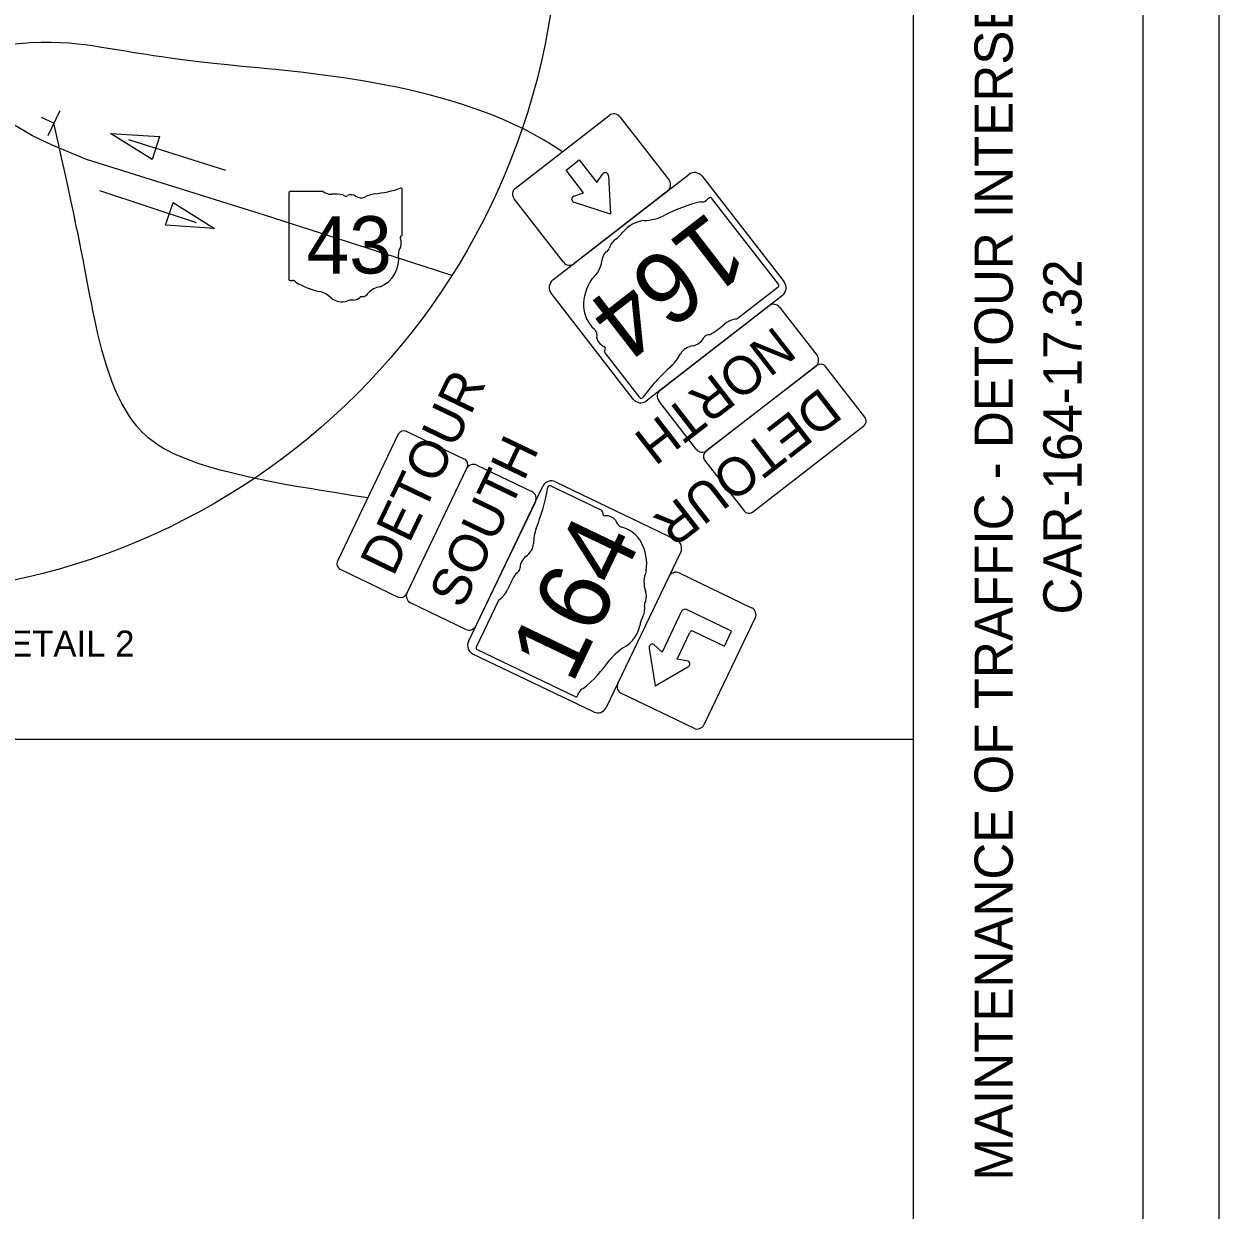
# Model space of a CAD drawing. Extents: x -202 to 1556, y 0 to 676.
# Drawn here: x 523.6 to 680, y 158.4 to 313.6 of the extents above; entities that cross this region are included whole.
import ezdxf

# ---------------------------------------------------------------- set-up
doc = ezdxf.new("R2010")
doc.units = 0
for name, color, linetype in [('Default', 7, 'Continuous'), ('GM_X_City_Street', 7, 'Continuous'), ('GM_X_Minor_Lake', 7, 'Continuous'), ('GM_X_Minor_River_Text', 7, 'Continuous'), ('SH_Border', 7, 'Continuous'), ('SH_Cut_Line', 7, 'Continuous'), ('SH_Data', 7, 'Continuous')]:
    doc.layers.add(name, color=color, linetype=linetype)

msp = doc.modelspace()

# ---------------------------------------------------------------- linework, layer by layer
at = {"layer": 'Default'}
for p, q in [((537.32, 298.48), (550.01, 294.47)), ((546.2, 287.58), (533.56, 291.75))]:
    msp.add_line(p, q, dxfattribs=at)
msp.add_lwpolyline([(579.61, 280.65), (575.86, 281.89), (555.1, 288.55), (531.8, 295.84), (527.22, 297.75), (524.76, 298.93), (522.29, 300.36), (520.6, 301.48), (519.03, 302.61), (517.4, 303.94), (515.97, 305.23), (514.31, 306.9), (512.8, 308.58), (510.9, 311.04), (509.31, 313.39), (508.43, 314.89), (507.69, 316.25), (506.99, 317.65), (506.47, 318.86), (505.75, 320.66), (505.24, 322.11), (504.47, 324.76), (503.95, 326.92), (503.59, 328.84)], dxfattribs=at)
for points in [[(540.42, 295.86), (534.94, 299.23), (541.36, 298.84)], [(543.13, 290.24), (548.57, 286.8), (542.15, 287.27)]]:
    msp.add_lwpolyline(points, close=True, dxfattribs=at)
at = {"layer": 'GM_X_City_Street'}
for p, q in [((558.3, 291.46), (558.3, 280.2)), ((562.79, 291.65), (558.45, 291.65)), ((573.13, 286.04), (573.13, 291.93)), ((573.13, 286.04), (573.13, 286.04))]:
    msp.add_line(p, q, dxfattribs=at)
for centre, radius, start, end in [((558.47, 291.48), 0.172, 98.1301, 188.1301), ((563.83, 292.96), 1.67, 231.6195, 271.1119), ((564.38, 285.33), 5.98, 80.4867, 94.9883), ((565.74, 291.54), 0.481, 219.7921, 297.1024), ((566.44, 290.24), 1, 54.4667, 119.1411), ((567.73, 292.02), 1.2, 233.8562, 294.8282), ((569.86, 288.21), 3.16, 97.3462, 120.7689), ((567.85, 307), 15.73, 275.8445, 288.9065), ((572.97, 291.95), 0.165, 351.8621, 97.738), ((573.1, 285.61), 0.256, 107.944, 210.337), ((571.47, 284.86), 1.53, 340.033, 23.6496), ((572.96, 286.02), 0.177, 289.6038, 7.7341), ((568.73, 282.83), 3.93, 292.3089, 8.9858), ((573.73, 283.58), 1.12, 136.8065, 186.9296), ((558.47, 280.17), 0.173, 171.9584, 258.3066), ((558.5, 281.33), 1.32, 267.339, 280.6039), ((558.77, 279.55), 0.477, 29.7484, 93.2717), ((564.79, 289.66), 11.36, 240.4129, 257.1985), ((561.41, 275.14), 3.55, 47.1842, 75.836), ((570.39, 277.04), 2.15, 94.4031, 142.5768), ((565.25, 279.49), 2.26, 230.7004, 286.2918), ((566.55, 275.6), 1.85, 85.6951, 111.2099), ((566.72, 278.65), 1.2, 268.777, 315.5493), ((567.81, 277.56), 0.338, 65.7517, 132.6484), ((567.66, 279.11), 1.27, 282.8732, 323.2771)]:
    msp.add_arc(centre, radius, start, end, dxfattribs=at)
at = {"layer": 'GM_X_Minor_Lake'}
for p, q in [((528.32, 302.21), (526.77, 298.96)), ((527.55, 300.58), (525.92, 301.36)), ((587.94, 292.11), (600.2, 301.61)), ((601.6, 301.43), (608.03, 293.13)), ((594.55, 294.46), (596.28, 295.8)), ((596.28, 295.8), (598.57, 292.84)), ((596.84, 291.5), (594.55, 294.46)), ((598.57, 292.84), (599.34, 293.94)), ((600.1, 293.72), (600.39, 288.71)), ((595.58, 291.03), (596.84, 291.5)), ((607.85, 291.73), (595.6, 282.23)), ((594.2, 282.41), (587.77, 290.71)), ((600.39, 288.71), (595.68, 290.22)), ((622.34, 279.52), (613.62, 290.76)), ((616.88, 274.98), (622.31, 279.18)), ((606.86, 265.66), (621.09, 276.69)), ((622.49, 276.51), (627.4, 270.19)), ((599.62, 270.57), (604.18, 264.69)), ((599.62, 270.57), (599.62, 270.57)), ((627.22, 268.78), (612.99, 257.76)), ((611.59, 257.93), (606.69, 264.26)), ((573.75, 239.16), (581.53, 255.39)), ((582.87, 255.86), (590.08, 252.4)), ((599.22, 249.92), (592.51, 253.14)), ((590.55, 251.07), (582.76, 234.84)), ((599.22, 249.92), (599.22, 249.92)), ((601.33, 227.31), (608.04, 241.29)), ((609.37, 241.76), (618.84, 237.21)), ((581.43, 234.37), (574.21, 237.83)), ((585.76, 238.25), (582.79, 232.06)), ((609.68, 236.76), (607.11, 231.4)), ((609.68, 236.76), (609.68, 236.76)), ((616.22, 234.14), (610.3, 236.98)), ((619.31, 235.88), (612.6, 221.9)), ((609.08, 230.46), (610.77, 233.98)), ((611.19, 234.13), (615.28, 232.17)), ((615.28, 232.17), (616.22, 234.14)), ((582.91, 231.75), (595.74, 225.59)), ((605.45, 231.87), (606.2, 226.99)), ((607.11, 231.4), (606.02, 232.39)), ((610.53, 230.22), (609.08, 230.46)), ((606.2, 226.99), (610.49, 229.46)), ((611.27, 221.44), (601.8, 225.98))]:
    msp.add_line(p, q, dxfattribs=at)
for points in [[(592.83, 280.09), (610.62, 293.87)], [(612.37, 293.65), (623.09, 279.82)], [(603.33, 264.51), (592.61, 278.34)], [(622.87, 278.07), (605.09, 264.28)], [(627.38, 268.91), (612.83, 257.63)], [(633.64, 262.12), (628.5, 268.76)], [(572.6, 259.9), (564.64, 243.31)], [(581.24, 256.64), (573.67, 260.27)], [(618.96, 249.73), (633.5, 261)], [(612.69, 256.51), (617.84, 249.87)], [(573.66, 238.98), (581.62, 255.57)], [(593.19, 253.68), (608.97, 246.11)], [(581.79, 232.81), (591.52, 253.09)], [(609.55, 244.44), (599.82, 224.16)], [(565.02, 242.24), (572.59, 238.61)], [(598.15, 223.57), (582.37, 231.14)]]:
    msp.add_lwpolyline(points, dxfattribs=at)
for centre, radius, start, end in [((600.81, 300.82), 1, 37.7759, 127.7759), ((599.68, 293.7), 0.417, 3.1871, 144.9805), ((611.38, 292.89), 1.25, 37.7759, 127.7759), ((607.24, 292.52), 1, 307.7759, 37.7759), ((588.56, 291.32), 1, 127.7759, 217.7759), ((595.73, 290.64), 0.417, 110.5713, 262.7854), ((594.99, 283.02), 1, 217.7759, 307.7759), ((593.6, 279.1), 1.25, 127.7759, 217.7759), ((622.1, 279.05), 1.25, 307.7759, 37.7759), ((621.7, 275.9), 1, 37.7759, 127.7759), ((626.6, 269.57), 1, 307.7759, 37.7759), ((627.87, 268.27), 0.8, 37.7759, 127.7759), ((604.32, 265.27), 1.25, 217.7759, 307.7759), ((607.48, 264.87), 1, 127.7759, 217.7759), ((633.01, 261.63), 0.8, 307.7759, 37.7759), ((573.32, 259.55), 0.8, 64.3687, 154.3687), ((580.9, 255.92), 0.8, 334.3687, 64.3687), ((612.38, 258.55), 1, 217.7759, 307.7759), ((613.32, 257), 0.8, 127.7759, 217.7759), ((582.43, 254.96), 1, 64.3687, 154.3687), ((592.65, 252.55), 1.25, 64.3687, 154.3687), ((589.65, 251.5), 1, 334.3687, 64.3687), ((618.47, 250.36), 0.8, 217.7759, 307.7759), ((608.43, 244.98), 1.25, 334.3687, 64.3687), ((565.36, 242.96), 0.8, 154.3687, 244.3687), ((608.94, 240.85), 1, 64.3687, 154.3687), ((572.94, 239.33), 0.8, 244.3687, 334.3687), ((574.65, 238.73), 1, 154.3687, 244.3687), ((610.1, 236.55), 0.469, 64.3687, 154.3687), ((618.41, 236.31), 1, 334.3687, 64.3687), ((581.86, 235.27), 1, 244.3687, 334.3687), ((611.06, 233.84), 0.312, 64.3687, 154.3687), ((582.92, 232.27), 1.25, 154.3687, 244.3687), ((605.84, 232.01), 0.417, 64.3703, 199.3685), ((610.35, 229.85), 0.417, 289.3688, 64.3703), ((602.24, 226.88), 1, 154.3687, 244.3687), ((598.69, 224.7), 1.25, 244.3687, 334.3687), ((611.7, 222.34), 1, 244.3687, 334.3687)]:
    msp.add_arc(centre, radius, start, end, dxfattribs=at)
for centre, major_axis, start_param, end_param in [((613.39, 290.62), (-0.217, -0.168), 3.00124, 4.508301), ((612.84, 275.02), (-14.19, -10.99), 4.195997, 4.488961), ((612.53, 290.96), (-0.596, -0.462), 0.519207, 1.627899), ((614.25, 289.45), (-1.65, -1.28), 4.665946, 4.897461), ((604.4, 284.74), (-2.82, -2.18), 4.026481, 4.996735), ((605.83, 292.81), (-4.44, -3.44), 0.823519, 1.323587), ((599.76, 287.37), (-2.31, -1.79), 1.495662, 1.94098), ((601.91, 284.17), (-1.5, -1.16), 4.691044, 5.507374), ((601.09, 282.8), (-1.59, -1.23), 4.937069, 5.64225), ((599.71, 284.2), (-0.423, -0.327), 1.147584, 2.315152), ((596.08, 282.22), (-2.69, -2.09), 1.647645, 2.488434), ((602.63, 278.04), (-4.91, -3.81), 5.101752, 6.440018), ((622.15, 279.33), (-0.215, -0.166), 1.712693, 3.28349), ((610.01, 279.76), (-7.47, -5.79), 1.404758, 1.657858), ((616.6, 272.67), (-2.08, -1.61), 4.042523, 4.731795), ((596.97, 272.46), (-1.39, -1.08), 2.387724, 3.262537), ((600.79, 273.36), (-1.92, -1.48), 5.934695, 6.695948), ((611.23, 272.85), (-1.25, -0.97), 0.950623, 2.079405), ((613.12, 272.24), (-0.601, -0.465), 3.836095, 5.185415), ((599.33, 271.04), (-0.319, -0.247), 1.883978, 3.671073), ((599.82, 270.76), (-0.221, -0.171), 5.05454, 6.418171), ((611, 269.82), (-1.5, -1.16), 4.081561, 5.145723), ((605.4, 271.57), (-3.95, -3.06), 1.699011, 2.107814), ((622.45, 254.75), (-19.65, -15.23), 4.814394, 5.042369), ((604.41, 264.82), (-0.206, -0.16), 6.141152, 7.989035), ((571.73, 253.85), (10.75, 22.41), 4.814394, 5.042369), ((592.37, 252.92), (0.113, 0.235), 6.141152, 7.989035), ((599.13, 249.65), (0.121, 0.252), 5.05454, 6.418171), ((599.69, 249.63), (0.175, 0.364), 1.883978, 3.671073), ((599.43, 246.9), (1.05, 2.19), 5.934695, 6.695948), ((602.44, 249.41), (0.76, 1.59), 2.387724, 3.262537), ((594.51, 246.44), (2.16, 4.51), 1.699011, 2.107814), ((599.88, 241.89), (2.69, 5.6), 5.101752, 6.440018), ((588.71, 245.49), (0.82, 1.71), 4.081561, 5.145723), ((587.9, 242.39), (0.329, 0.685), 3.836095, 5.185415), ((589.87, 242.68), (0.68, 1.42), 0.950623, 2.079405), ((594.05, 237.06), (4.09, 8.52), 1.404758, 1.657858), ((607.61, 241.09), (1.47, 3.07), 1.647645, 2.488434), ((584.98, 240.44), (1.14, 2.37), 4.042523, 4.731795), ((603.38, 238.33), (0.87, 1.81), 4.937069, 5.64225), ((605.25, 237.69), (0.231, 0.482), 1.147584, 2.315152), ((603.26, 236.74), (0.82, 1.71), 4.691044, 5.507374), ((601.3, 235.11), (1.54, 3.21), 4.026481, 4.996735), ((606.62, 234.83), (1.27, 2.64), 1.495662, 1.94098), ((583, 232), (0.117, 0.245), 1.712693, 3.28349), ((603.63, 227.25), (2.43, 5.06), 0.823519, 1.323587), ((589.39, 240.01), (7.76, 16.18), 4.195997, 4.488961), ((595.89, 225.82), (0.118, 0.247), 3.00124, 4.508301), ((594.59, 226.49), (0.9, 1.88), 4.665946, 4.897461), ((596.8, 225.9), (0.326, 0.68), 0.519207, 1.627899)]:
    msp.add_ellipse(centre, major_axis=major_axis, ratio=0.8, start_param=start_param, end_param=end_param, dxfattribs=at)
at = {"layer": 'GM_X_Minor_River_Text'}
msp.add_line((30, 220), (640, 220), dxfattribs=at)
at = {"layer": 'SH_Border'}
msp.add_line((640, 10), (640, 430), dxfattribs=at)
msp.add_lwpolyline([(30, 430), (670, 430), (670, 10), (30, 10)], close=True, dxfattribs=at)
at = {"layer": 'SH_Cut_Line'}
msp.add_lwpolyline([(0, 0), (680, 0), (680, 440), (0, 440)], close=True, dxfattribs=at)
at = {"layer": 'SH_Data'}
msp.add_circle((503.59, 328.84), 90, dxfattribs=at)
for points in [[(594.07, 296.86), (581.34, 305.55), (544.58, 308.38), (535.1, 310.52), (522.4, 312.09), (508.65, 308.06)], [(568.62, 251.6), (545.28, 254.94), (535.71, 260.38), (531.98, 279.31), (530.62, 286.88), (527.55, 300.58)]]:
    msp.add_open_spline(points, degree=3, dxfattribs=at)

# ---------------------------------------------------------------- texts
at = {"layer": 'GM_X_City_Street'}
msp.add_text('43', height=7.5, dxfattribs=at).set_placement((560.6, 280.93))
at = {"layer": 'GM_X_Minor_Lake'}
for s, height, rotation, p in [('164', 9.375, 217.7759, (613.33, 289.27)), ('NORTH', 5, 217.7759, (621.94, 274.18)), ('DETOUR', 5, 64.3687, (571.94, 241.17)), ('DETOUR', 5, 217.7759, (627.93, 266.17)), ('SOUTH', 5, 64.3687, (580.98, 236.9)), ('164', 9.375, 64.3687, (595.33, 227.06))]:
    msp.add_text(s, height=height, rotation=rotation, dxfattribs=at).set_placement(p)
at = {"layer": 'GM_X_Minor_River_Text'}
msp.add_text('DETOUR INTERSECTION DETAIL 2', height=3.4, dxfattribs=at).set_placement((462.81, 230.82))
at = {"layer": 'SH_Data'}
for s, p in [('MAINTENANCE OF TRAFFIC - DETOUR INTERSECTION DETAILS', (653, 162.26)), ('CAR-164-17.32', (662, 236.32))]:
    msp.add_text(s, height=5, rotation=90, dxfattribs=at).set_placement(p)

doc.saveas('drawing.dxf')
